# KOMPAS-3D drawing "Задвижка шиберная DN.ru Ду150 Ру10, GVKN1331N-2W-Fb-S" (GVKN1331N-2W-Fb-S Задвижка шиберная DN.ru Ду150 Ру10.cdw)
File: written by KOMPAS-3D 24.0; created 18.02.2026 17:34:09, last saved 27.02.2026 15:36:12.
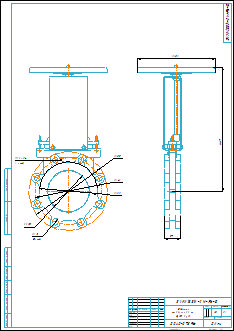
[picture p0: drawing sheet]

Document properties: art: D040-07896; Автор: R2D2; Форматы листов документа: A2; Полное имя файла: GVKN1331N-2W-Fb-S Задвижка шиберная DN.ru Ду150 Ру10.m3d; Масса: 18; Наименование: Задвижка шиберная DN.ru Ду150 Ру10; Количество листов документа: 1; Примечание: D040-07896

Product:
- Part/product: Задвижка шиберная DN.ru Ду150 Ру10  | designation GVKN1331N-2W-Fb-S
    Масса: 18
    Раздел спецификации: Прочие изделия
    Форматы листов документа: A2
    Примечание: D040-07896
    additional columns: D040-07896

Views: Вид 1, Спереди, Проекционный вид 2
Referenced files in E:\Работа\Зайцев\GVKN1331N-2W-Fb-S Задвижка шиберная DN.ru Ду50-300 Ру10\DN150\: GVKN1331N-2W-Fb-S Задвижка шиберная DN.ru Ду150 Ру10.m3d
Referenced files in E:\Работа\Зайцев\Для компаса\: чертеж DN.ru.cdt
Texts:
  GVKN1331N-2W-Fb-S
  чертеж DN.ru.cdt
  Задвижка
  шиберная DN.ru
  Ду150 Ру10
  prop
  Задвижка шиберная DN.ru Ду150 Ру10
  GVKN1331N-2W-Fb-S Задвижка шиберная DN.ru Ду150 Ру10
Dimensions and other numbers on the sheet: 0; 3; 2; 4; 285; 240; 211; 150; 23; 6 отв.; 20; 2 отв.; 57; 447; 280; 1:2; 1; 18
